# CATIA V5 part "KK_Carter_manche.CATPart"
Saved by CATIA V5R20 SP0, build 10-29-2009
Part number: Carter_manche
Bounding box of the stored display mesh (mm): x -12.5 to 12.5, y 0 to 125, z -25 to 25
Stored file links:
  G:\Khaled_CFAO_2011\ST2M\ST2M_GR2\aandujar\Khaled\CAD_thinkMOTION\KK_Carter_manche.CATPart
  G:\Khaled_CFAO_2011\ST2M\ST2M_GR2\aandujar\Khaled\CAD_thinkMOTION\KK_Aandujar.CATProduct
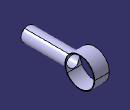
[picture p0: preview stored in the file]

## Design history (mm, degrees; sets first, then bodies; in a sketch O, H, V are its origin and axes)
WSupportSet1: ActiveGrid {3dwsupport RefPoint {point stored without definition}, 3DWOS ({wsupport Support xy-plane, RefPoint {3dwsupport}, GridIn {cartgrid Value 100, Stepbid1 0, Value 100, Stepbid2 0, Direction (1, 0, 0)}, GeometricData ({line type PtDir, Direction (1, 0, 0), Support xy-plane}; {line type PtDir, Direction (0, 1, 0), Support yz-plane})}; {wsupport Support yz-plane, RefPoint {3dwsupport}, GridIn {cartgrid Value 100, Stepbid1 0, Value 100, Stepbid2 0, Direction (0, 1, 0)}, GeometricData ({line type PtDir, Direction (0, 1, 0), Support yz-plane}; {line type PtDir, Direction (0, 0, 1), Support zx-plane})}; {wsupport Support zx-plane, RefPoint {3dwsupport}, GridIn {cartgrid Value 100, Stepbid1 0, Value 100, Stepbid2 0, Direction (0, 0, 1)}, GeometricData ({line type PtDir, Direction (0, 0, 1), Support zx-plane}; {line type PtDir, Direction (1, 0, 0), Support xy-plane})}), GeometricData ({line type PtDir, RefPoint {point stored without definition}, Direction (1, 0, 0), Support xy-plane}; {line type PtDir, RefPoint {point stored without definition}, Direction (0, 1, 0), Support yz-plane}; {line type PtDir, RefPoint {point stored without definition}, Direction (0, 0, 1), Support zx-plane})}
Set1
  Sketch1 on Plane1, origin (0, 0, 0), H (0, 1, 0), V (0, 0, 1)
    point P1 (0, 0)
    line L1 (0, 0) -> (0, 12)
    line L2 (0, 12) -> (100, 12)
    line L3 (100, 12) -> (100, 0)
    point P4 (100, 0)
    line L4 (100, 0) -> (0, 0)
    reference projected point E1 (100, 0) from Point1
    reference projected point E2 (0, 0) from Point2
    distance L2 L4 = 12
    coincidence: P1 H, P4 H, P4 E1, P1 E2
    vertical: L1 V, L3 V
    horizontal: L2 H, L4 H
Set2
  Plane1 "Plan_Ref1": linked copy from another document
  Point1: linked copy from another document
  Point2: linked copy from another document
Body1 (main body)
  Shaft1: profile Sketch1, axis Sketch1.L4, angle 360
  Sketch2 on Plane1, origin (0, 0, 0), H (0, 1, 0), V (0, 0, 1)
    circle A1 centre (100, 0) radius 25
    point P1 (100, 0)
    reference projected point E1 (100, 0) from Point1
    radius A1 = 25
    coincidence: P1 E1
  Pad1: profile Sketch2, direction (1, 0, 0), length 12.5, mirrored extent
  Sketch3 on start face of Pad1, origin (-12.5, 100, 0), H (0, 1, 0), V (0, 0, -1)
    point P1 (0, 0)
    construction circle A1 centre (0, 0) radius 24
    point P2 (0, 0)
    reference projected point E1 (0, 0) from Point1
    radius A1 = 24
    coincidence: P2 E1
  Hole1: placed by Sketch3, at (-12.5, 100, 0) direction (1, 0, 0), diameter 48, through (limit type 6)
  Sketch4 on face of Shaft1 from Sketch1.L1, origin (0, 0, 0), H (1, 0, 0), V (0, 0, 1)
    point P1 (0, 0)
    construction circle A1 centre (0, 0) radius 10
    point P2 (0, 0)
    reference projected point E1 (0, 0) from Point2
    radius A1 = 10
    coincidence: P2 E1
  Hole2: placed by Sketch4, at (0, 0, 0) direction (0, 1, 0), diameter 21, through (limit type 6)
  Sketch5 on start face of Pad1, origin (-12.5, 0, 0), H (0, -1, 0), V (0, 0, 1)
    circle A1 centre (-100, 0) radius 25
    point P1 (-100, 0)
    reference projected point E1 (-100, 0) from Point1
    reference projected circle E2 centre (-100, 0) radius 25 from edge [start face of Pad1 | face of Pad1 from Sketch2.A1]
    coincidence: E1 P1, A1 E2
